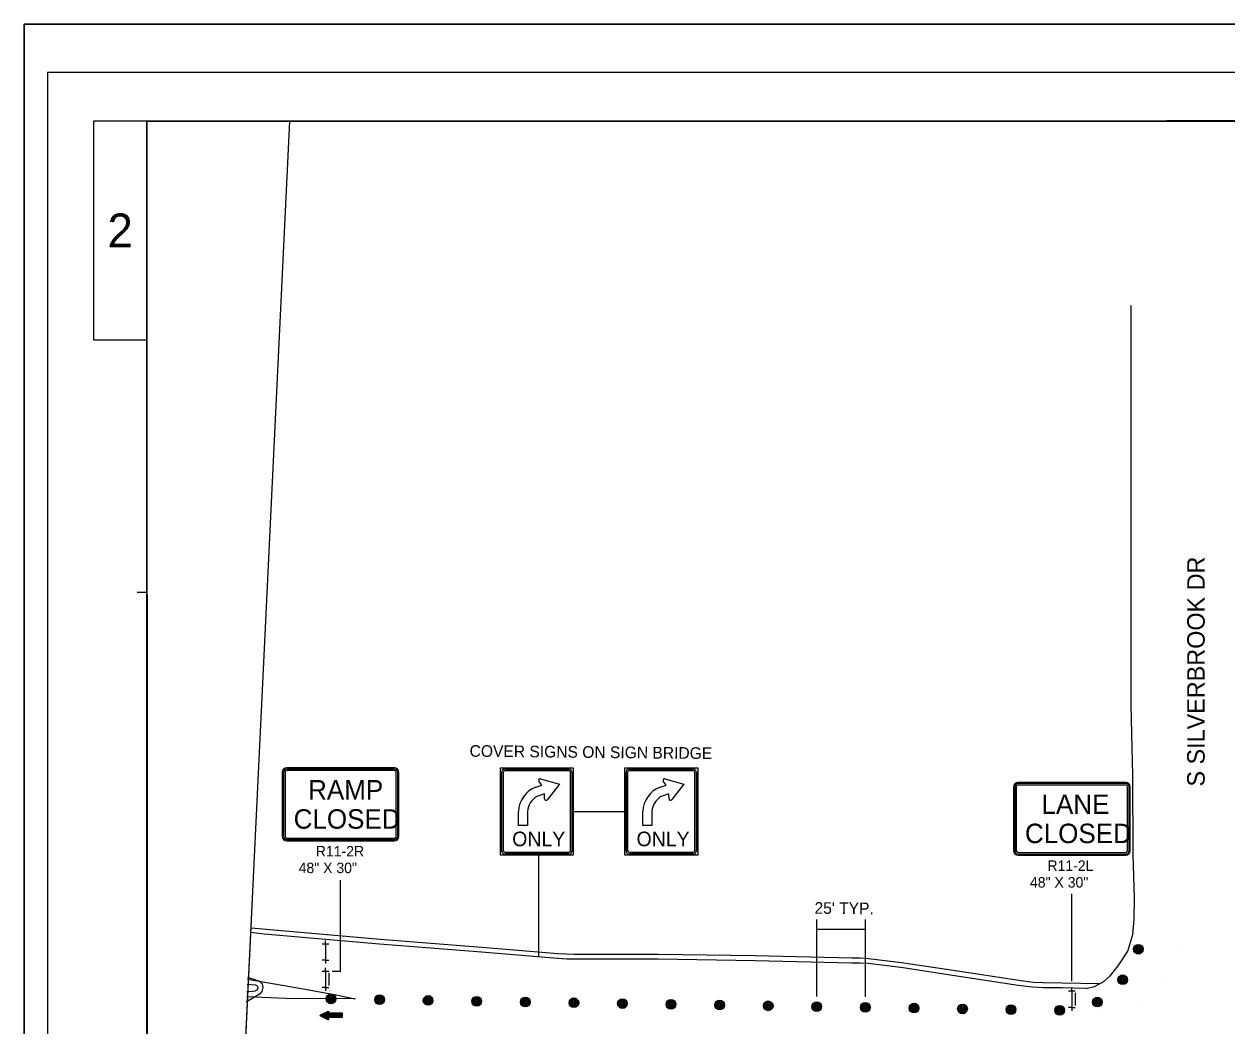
# Model space of a CAD drawing. Extents: x 360065 to 362124, y 174333 to 175433.
# Drawn here: x 360424 to 361043, y 174917 to 175433 of the extents above; entities that cross this region are included whole.
import ezdxf

# ---------------------------------------------------------------- set-up
doc = ezdxf.new("R2010")
doc.units = 0
for name, color, linetype in [('Default', 7, 'Continuous'), ('P_ALI_100_PIData', 7, 'Continuous'), ('P_ALI_100_Sta', 7, 'Continuous'), ('P_ALI_20', 7, 'Continuous'), ('P_ALI_200_Equation', 7, 'Continuous'), ('P_ALI_20_Equation', 7, 'Continuous'), ('P_ALI_20_Sta', 7, 'Continuous'), ('P_ALI_20_Tic', 7, 'Continuous'), ('P_ALI_500_PIData', 7, 'Continuous'), ('P_ALI_500_Sta', 7, 'Continuous'), ('P_ALI_50_Equation', 7, 'Continuous'), ('P_ALI_50_Tic', 7, 'Continuous'), ('P_TC_Drums_100_50', 7, 'Continuous')]:
    doc.layers.add(name, color=color, linetype=linetype)

msp = doc.modelspace()

# ---------------------------------------------------------------- linework, layer by layer
for p, q in [((360424.11, 175382.95), (360424.11, 175432.95)), ((360424.11, 175432.95), (360474.11, 175432.95)), ((360487.36, 175382.95), (362062.36, 175382.95)), ((360487.36, 174382.95), (360487.36, 175382.95)), ((360487.36, 175140.45), (360482.36, 175140.45))]:
    msp.add_line(p, q)
msp.add_lwpolyline([(360487.36, 175382.95), (360459.86, 175382.95), (360459.86, 175270.45), (360487.36, 175270.45)], close=True)
at = {"layer": 'Default'}
msp.add_lwpolyline([(362007.43, 175382.95), (362007.43, 174984.32), (362007.43, 174408.5), (360513.97, 174407.95), (360560.89, 175382.95)], close=True, dxfattribs=at)
msp.add_lwpolyline([(362007.43, 175382.95), (362007.43, 174984.32), (362007.43, 174408.5), (360513.97, 174407.95), (360560.89, 175382.95)], close=True, dxfattribs=at)
msp.add_lwpolyline([(362007.43, 175382.95), (362007.43, 174984.32), (362007.43, 174408.5), (360513.97, 174407.95), (360560.89, 175382.95)], close=True, dxfattribs=at)
at = {"layer": 'P_ALI_100_PIData'}
for p, q in [((360704.39, 175048.72), (360671.58, 175048.72)), ((360768.37, 175048.72), (360735.56, 175048.72)), ((360670.64, 175047.79), (360670.64, 175007.47)), ((360705.33, 175007.47), (360705.33, 175047.79)), ((360734.62, 175047.79), (360734.62, 175007.47)), ((360769.31, 175007.47), (360769.31, 175047.79)), ((360706.74, 175027.63), (360733.22, 175027.63)), ((360671.58, 175006.54), (360704.39, 175006.54)), ((360735.56, 175006.54), (360768.37, 175006.54)), ((360688.98, 174952.75), (360688.98, 175005.13)), ((360586.99, 174945.53), (360586.99, 174992.36)), ((360963.29, 174940.29), (360963.29, 174985.23)), ((360832, 174932.37), (360832, 174972.09)), ((360857, 174932.28), (360857, 174972.09)), ((360832, 174967.09), (360857, 174967.09)), ((360582.64, 174945.53), (360586.99, 174945.53))]:
    msp.add_line(p, q, dxfattribs=at)
for centre, start, end in [((360671.58, 175047.79), 90, 180), ((360704.39, 175047.79), 360, 90), ((360735.56, 175047.79), 90, 180), ((360768.37, 175047.79), 360, 90), ((360671.58, 175007.47), 180, 270), ((360704.39, 175007.47), 270, 0), ((360735.56, 175007.47), 180, 270), ((360768.37, 175007.47), 270, 0)]:
    msp.add_arc(centre, 0.938, start, end, dxfattribs=at)
at = {"layer": 'P_ALI_100_Sta'}
for p, q in [((360577.47, 174959.58), (360579.17, 174959.58)), ((360579.17, 174959.58), (360579.17, 174961.28)), ((360579.17, 174959.58), (360580.87, 174959.58)), ((360579.17, 174959.58), (360579.17, 174951.08)), ((361019.91, 174956.41), (361019.91, 174956.41)), ((360579.17, 174951.08), (360577.47, 174951.08)), ((360579.17, 174951.08), (360580.87, 174951.08)), ((360579.17, 174951.08), (360579.17, 174949.38)), ((360577.47, 174945.53), (360579.17, 174945.53)), ((360579.17, 174945.53), (360579.17, 174947.23)), ((360579.17, 174945.53), (360580.87, 174945.53)), ((360579.17, 174945.53), (360579.17, 174937.03)), ((360580.87, 174944.53), (360580.87, 174938.03)), ((361011.91, 174940.66), (361011.91, 174940.66)), ((360579.17, 174937.03), (360577.47, 174937.03)), ((360579.17, 174937.03), (360580.87, 174937.03)), ((360579.17, 174937.03), (360579.17, 174935.33)), ((360961.59, 174935.29), (360963.29, 174935.29)), ((360963.29, 174935.29), (360963.29, 174936.99)), ((360963.29, 174935.29), (360964.99, 174935.29)), ((360963.29, 174935.29), (360963.29, 174926.79)), ((360964.99, 174934.29), (360964.99, 174927.79)), ((360604.53, 174930.86), (360604.53, 174930.86)), ((360629.53, 174930.42), (360629.53, 174930.42)), ((360654.53, 174930.02), (360654.53, 174930.02)), ((360679.52, 174929.63), (360679.52, 174929.63)), ((360704.52, 174929.23), (360704.52, 174929.23)), ((360729.52, 174928.83), (360729.52, 174928.83)), ((360754.51, 174928.44), (360754.51, 174928.44)), ((360779.51, 174928.04), (360779.51, 174928.04)), ((360804.51, 174927.65), (360804.51, 174927.65)), ((360829.5, 174927.26), (360829.5, 174927.26)), ((360854.5, 174926.87), (360854.5, 174926.87)), ((360879.5, 174926.48), (360879.5, 174926.48)), ((360904.49, 174926.09), (360904.49, 174926.09)), ((360929.49, 174925.69), (360929.49, 174925.69)), ((360954.49, 174925.3), (360954.49, 174925.3)), ((360963.29, 174926.79), (360961.59, 174926.79)), ((360963.29, 174926.79), (360964.99, 174926.79)), ((360963.29, 174926.79), (360963.29, 174925.09)), ((360979.49, 174924.91), (360979.49, 174924.91)), ((360998.84, 174929.19), (360998.84, 174929.19))]:
    msp.add_line(p, q, dxfattribs=at)
for centre, radius in [((360997.42, 174956.76), 2.5), ((360997.42, 174956.76), 2), ((360997.42, 174956.76), 1.5), ((360997.42, 174956.76), 1), ((360997.42, 174956.76), 0.5), ((360997.42, 174956.76), 0.25), ((360989.42, 174941.02), 2.5), ((360989.42, 174941.02), 2), ((360989.42, 174941.02), 1.5), ((360989.42, 174941.02), 1), ((360989.42, 174941.02), 0.5), ((360989.42, 174941.02), 0.25), ((360582.04, 174931.21), 2.5), ((360582.04, 174931.21), 2), ((360582.04, 174931.21), 1.5), ((360582.04, 174931.21), 1), ((360582.04, 174931.21), 0.5), ((360582.04, 174931.21), 0.25), ((360607.03, 174930.78), 2.5), ((360607.03, 174930.78), 2), ((360607.03, 174930.78), 1.5), ((360607.03, 174930.78), 1), ((360607.03, 174930.78), 0.5), ((360607.03, 174930.78), 0.25), ((360632.03, 174930.38), 2.5), ((360632.03, 174930.38), 2), ((360632.03, 174930.38), 1.5), ((360632.03, 174930.38), 1), ((360657.03, 174929.98), 2.5), ((360657.03, 174929.98), 2), ((360657.03, 174929.98), 1.5), ((360657.03, 174929.98), 1), ((360682.02, 174929.58), 2.5), ((360682.02, 174929.58), 2), ((360682.02, 174929.58), 1.5), ((360707.02, 174929.18), 2.5), ((360707.02, 174929.18), 2), ((360732.02, 174928.79), 2.5), ((360976.35, 174929.54), 2.5), ((360976.35, 174929.54), 2), ((360976.35, 174929.54), 1.5), ((360632.03, 174930.38), 0.5), ((360632.03, 174930.38), 0.25), ((360657.03, 174929.98), 0.5), ((360657.03, 174929.98), 0.25), ((360682.02, 174929.58), 1), ((360682.02, 174929.58), 0.5), ((360682.02, 174929.58), 0.25), ((360707.02, 174929.18), 1.5), ((360707.02, 174929.18), 1), ((360707.02, 174929.18), 0.5), ((360707.02, 174929.18), 0.25), ((360732.02, 174928.79), 2), ((360732.02, 174928.79), 1.5), ((360732.02, 174928.79), 1), ((360732.02, 174928.79), 0.5), ((360732.02, 174928.79), 0.25), ((360757.01, 174928.4), 2.5), ((360757.01, 174928.4), 2), ((360757.01, 174928.4), 1.5), ((360757.01, 174928.4), 1), ((360757.01, 174928.4), 0.5), ((360757.01, 174928.4), 0.25), ((360782.01, 174928.01), 2.5), ((360782.01, 174928.01), 2), ((360782.01, 174928.01), 1.5), ((360782.01, 174928.01), 1), ((360782.01, 174928.01), 0.5), ((360782.01, 174928.01), 0.25), ((360807.01, 174927.61), 2.5), ((360807.01, 174927.61), 2), ((360807.01, 174927.61), 1.5), ((360807.01, 174927.61), 1), ((360807.01, 174927.61), 0.5), ((360807.01, 174927.61), 0.25), ((360832, 174927.22), 2.5), ((360832, 174927.22), 2), ((360832, 174927.22), 1.5), ((360832, 174927.22), 1), ((360832, 174927.22), 0.5), ((360832, 174927.22), 0.25), ((360857, 174926.83), 2.5), ((360857, 174926.83), 2), ((360857, 174926.83), 1.5), ((360857, 174926.83), 1), ((360857, 174926.83), 0.5), ((360857, 174926.83), 0.25), ((360882, 174926.44), 2.5), ((360882, 174926.44), 2), ((360882, 174926.44), 1.5), ((360882, 174926.44), 1), ((360882, 174926.44), 0.5), ((360882, 174926.44), 0.25), ((360906.99, 174926.05), 2.5), ((360906.99, 174926.05), 2), ((360906.99, 174926.05), 1.5), ((360906.99, 174926.05), 1), ((360906.99, 174926.05), 0.5), ((360906.99, 174926.05), 0.25), ((360931.99, 174925.65), 2.5), ((360931.99, 174925.65), 2), ((360931.99, 174925.65), 1.5), ((360931.99, 174925.65), 1), ((360931.99, 174925.65), 0.5), ((360931.99, 174925.65), 0.25), ((360956.99, 174925.26), 2.5), ((360956.99, 174925.26), 2), ((360956.99, 174925.26), 1.5), ((360956.99, 174925.26), 1), ((360956.99, 174925.26), 0.5), ((360956.99, 174925.26), 0.25), ((360976.35, 174929.54), 1), ((360976.35, 174929.54), 0.5), ((360976.35, 174929.54), 0.25)]:
    msp.add_circle(centre, radius, dxfattribs=at)
at = {"layer": 'P_ALI_20'}
for points in [[(360424.11, 174332.95), (362124.11, 174332.95), (362124.11, 175432.95), (360424.11, 175432.95)], [(360436.11, 174357.95), (362091.11, 174357.95), (362091.11, 175407.95), (360436.11, 175407.95)]]:
    msp.add_lwpolyline(points, close=True, dxfattribs=at)
at = {"layer": 'P_ALI_200_Equation'}
msp.add_lwpolyline([(360424.11, 175432.95), (362124.11, 175432.95), (362124.11, 174332.95), (360424.11, 174332.95), (360424.11, 175432.95)], dxfattribs=at)
at = {"layer": 'P_ALI_20_Equation'}
msp.add_line((360993.75, 175082.17), (360993.75, 175288.17), dxfattribs=at)
for points in [[(360970.58, 174936.56), (360970.58, 174936.56), (360970.58, 174936.56), (360970.58, 174936.56), (360970.58, 174936.56), (360974.85, 174937.53), (360979.64, 174940.2), (360983.1, 174943.25), (360987.12, 174948.28), (360992.14, 174955.78), (360994.64, 174964.37), (360995.33, 174972.21), (360995.44, 174983.02), (360994.88, 175005.27), (360994.61, 175046.09), (360993.75, 175082.17)], [(360970.58, 174936.56), (360970.58, 174936.56), (360958.29, 174936.82), (360948.46, 174936.95), (360943.08, 174937.2), (360935.6, 174938.11), (360901.84, 174943.28), (360876.44, 174947.15), (360868.17, 174948.17), (360858.37, 174949.37), (360854.23, 174949.58), (360850.06, 174949.59), (360800.28, 174950.8), (360750.37, 174951.56), (360706.92, 174951.58), (360703.36, 174951.63), (360698.54, 174951.96), (360659.5, 174955.21), (360607.07, 174959.3), (360547.62, 174964.46), (360540.79, 174965.31)], [(360977.33, 174938.91), (360958.33, 174939.32), (360948.54, 174939.44), (360943.29, 174939.69), (360935.94, 174940.59), (360902.22, 174945.76), (360876.78, 174949.63), (360868.48, 174950.65), (360858.59, 174951.86), (360854.3, 174952.08), (360850.1, 174952.09), (360800.32, 174953.3), (360750.39, 174954.06), (360706.94, 174954.08), (360703.46, 174954.13), (360698.73, 174954.45), (360659.71, 174957.7), (360607.27, 174961.79), (360540.9, 174967.55)], [(360539.08, 174942.35), (360545.27, 174940.34), (360546.55, 174938.92), (360546.96, 174936.98), (360546.52, 174935.08), (360545.21, 174933.63), (360538.46, 174929.54)], [(360539.03, 174941.35), (360565.88, 174936.74), (360583.83, 174933.52), (360594.49, 174931.26), (360558.8, 174931.46), (360538.59, 174932.2)], [(360538.9, 174938.81), (360543.16, 174938.4), (360543.86, 174938.17), (360544.24, 174937.75), (360544.4, 174937.01), (360544.23, 174936.28), (360543.6, 174935.58), (360542.92, 174935.17), (360541.9, 174935), (360538.71, 174934.83)]]:
    msp.add_lwpolyline(points, dxfattribs=at)
at = {"layer": 'P_ALI_20_Sta'}
msp.add_lwpolyline([(360424.11, 175432.95), (362124.11, 175432.95), (362124.11, 174332.95), (360424.11, 174332.95)], close=True, dxfattribs=at)
at = {"layer": 'P_ALI_20_Tic'}
msp.add_line((360531.68, 174775.82), (360541.63, 174982.64), dxfattribs=at)
at = {"layer": 'P_ALI_500_PIData'}
for p, q in [((360576.29, 174922.72), (360580.69, 174924.93)), ((360580.69, 174924.93), (360580.69, 174920.43)), ((360576.29, 174922.72), (360580.69, 174920.43)), ((360587.81, 174922.91), (360576.67, 174922.91)), ((360587.81, 174922.46), (360576.79, 174922.46)), ((360587.81, 174923.36), (360577.56, 174923.36)), ((360587.81, 174922.01), (360577.66, 174922.01)), ((360580.66, 174923.81), (360578.46, 174923.81)), ((360580.66, 174921.56), (360578.52, 174921.56)), ((360580.66, 174924.26), (360579.35, 174924.26)), ((360580.66, 174921.11), (360579.39, 174921.11)), ((360580.66, 174924.71), (360580.24, 174924.71)), ((360580.66, 174920.66), (360580.25, 174920.66)), ((360587.81, 174923.81), (360580.69, 174923.81)), ((360587.81, 174921.56), (360580.69, 174921.56)), ((360587.81, 174923.81), (360587.81, 174921.56)), ((360587.81, 174922.68), (360587.81, 174922.68))]:
    msp.add_line(p, q, dxfattribs=at)
at = {"layer": 'P_ALI_500_Sta'}
for p, q in [((360614.66, 175050.07), (360559.33, 175050.07)), ((360614.66, 175049.45), (360559.33, 175049.45)), ((360614.66, 175048.67), (360559.33, 175048.67)), ((360556.98, 175047.73), (360556.98, 175014.91)), ((360557.61, 175047.73), (360557.61, 175014.91)), ((360558.39, 175047.71), (360558.39, 175014.91)), ((360615.6, 175014.91), (360615.6, 175047.73)), ((360616.38, 175014.91), (360616.38, 175047.73)), ((360617, 175014.91), (360617, 175047.73)), ((360990.95, 175042.64), (360935.62, 175042.64)), ((360933.28, 175040.3), (360933.28, 175007.48)), ((360933.9, 175040.3), (360933.9, 175007.48)), ((360934.68, 175040.28), (360934.68, 175007.48)), ((360990.95, 175042.02), (360935.62, 175042.02)), ((360990.95, 175041.24), (360935.62, 175041.24)), ((360991.89, 175007.48), (360991.89, 175040.3)), ((360992.67, 175007.48), (360992.67, 175040.3)), ((360993.3, 175007.48), (360993.3, 175040.3)), ((360559.33, 175013.97), (360614.66, 175013.97)), ((360559.33, 175013.19), (360614.66, 175013.19)), ((360559.33, 175012.56), (360614.66, 175012.56)), ((360935.62, 175006.54), (360990.95, 175006.54)), ((360935.62, 175005.76), (360990.95, 175005.76)), ((360935.62, 175005.13), (360990.95, 175005.13))]:
    msp.add_line(p, q, dxfattribs=at)
for centre, radius, start, end in [((360559.33, 175047.73), 2.34, 90, 180), ((360559.33, 175047.73), 1.72, 90, 180), ((360559.33, 175047.73), 0.938, 90, 181.0779), ((360614.66, 175047.73), 2.34, 0, 90), ((360614.66, 175047.73), 1.72, 0, 90), ((360614.66, 175047.73), 0.938, 0, 90), ((360935.62, 175040.3), 2.34, 90, 180), ((360990.95, 175040.3), 2.34, 0, 90), ((360935.62, 175040.3), 1.72, 90, 180), ((360935.62, 175040.3), 0.938, 90, 181.0779), ((360990.95, 175040.3), 1.72, 0, 90), ((360990.95, 175040.3), 0.938, 0, 90), ((360559.33, 175014.91), 2.34, 180, 270), ((360559.33, 175014.91), 1.72, 180, 270), ((360559.33, 175014.91), 0.938, 180, 270), ((360614.66, 175014.91), 0.938, 270, 360), ((360614.66, 175014.91), 1.72, 270, 360), ((360614.66, 175014.91), 2.34, 270, 360), ((360935.62, 175007.48), 2.34, 180, 270), ((360935.62, 175007.48), 1.72, 180, 270), ((360935.62, 175007.48), 0.938, 180, 270), ((360990.95, 175007.48), 0.938, 270, 360), ((360990.95, 175007.48), 1.72, 270, 360), ((360990.95, 175007.48), 2.34, 270, 360)]:
    msp.add_arc(centre, radius, start, end, dxfattribs=at)
at = {"layer": 'P_ALI_50_Tic'}
msp.add_lwpolyline([(362062.02, 175383.5), (360487.36, 175382.95), (360487.7, 174407.95)], dxfattribs=at)
at = {"layer": 'P_TC_Drums_100_50'}
for p, q in [((360669.24, 175005.13), (360669.24, 175050.13)), ((360669.24, 175050.13), (360706.74, 175050.13)), ((360671.58, 175049.51), (360704.39, 175049.51)), ((360671.58, 175048.72), (360704.39, 175048.72)), ((360706.74, 175050.13), (360706.74, 175005.13)), ((360733.22, 175005.13), (360733.22, 175050.13)), ((360733.22, 175050.13), (360770.72, 175050.13)), ((360735.56, 175049.51), (360768.37, 175049.51)), ((360735.56, 175048.72), (360768.37, 175048.72)), ((360770.72, 175050.13), (360770.72, 175005.13)), ((360669.86, 175007.47), (360669.86, 175047.79)), ((360670.64, 175007.47), (360670.64, 175047.79)), ((360690.46, 175041.21), (360689.04, 175043.31)), ((360689.9, 175044.5), (360699.55, 175041.69)), ((360705.33, 175047.79), (360705.33, 175007.47)), ((360706.11, 175047.79), (360706.11, 175007.47)), ((360733.84, 175007.47), (360733.84, 175047.79)), ((360734.62, 175007.47), (360734.62, 175047.79)), ((360754.44, 175041.21), (360753.02, 175043.31)), ((360753.88, 175044.5), (360763.53, 175041.69)), ((360769.31, 175047.79), (360769.31, 175007.47)), ((360770.09, 175047.79), (360770.09, 175007.47)), ((360687.48, 175040.24), (360690.46, 175041.21)), ((360691.9, 175036.75), (360687.93, 175035.29)), ((360691.99, 175034.21), (360691.9, 175036.75)), ((360699.55, 175041.69), (360693.39, 175033.76)), ((360751.46, 175040.24), (360754.44, 175041.21)), ((360755.88, 175036.75), (360751.92, 175035.29)), ((360755.97, 175034.21), (360755.88, 175036.75)), ((360763.53, 175041.69), (360757.37, 175033.76)), ((360678.46, 175020.44), (360678.47, 175027.63)), ((360683.16, 175027.63), (360683.14, 175020.44)), ((360742.44, 175020.44), (360742.45, 175027.63)), ((360747.14, 175027.63), (360747.12, 175020.44)), ((360683.14, 175020.44), (360678.46, 175020.44)), ((360747.12, 175020.44), (360742.44, 175020.44)), ((360704.39, 175006.54), (360671.58, 175006.54)), ((360704.39, 175005.76), (360671.58, 175005.76)), ((360768.37, 175006.54), (360735.56, 175006.54)), ((360768.37, 175005.76), (360735.56, 175005.76)), ((360706.74, 175005.13), (360669.24, 175005.13)), ((360770.72, 175005.13), (360733.22, 175005.13))]:
    msp.add_line(p, q, dxfattribs=at)
for centre, radius, start, end in [((360671.58, 175047.79), 1.72, 90, 180), ((360671.58, 175047.79), 0.938, 90, 180), ((360704.39, 175047.79), 1.72, 0, 90), ((360704.39, 175047.79), 0.938, 0, 90), ((360735.56, 175047.79), 1.72, 90, 180), ((360735.56, 175047.79), 0.938, 90, 180), ((360768.37, 175047.79), 1.72, 0, 90), ((360768.37, 175047.79), 0.938, 0, 90), ((360689.68, 175043.75), 0.781, 73.78835, 214.03143), ((360753.66, 175043.75), 0.781, 73.78835, 214.03143), ((360692.67, 175027.01), 14.22, 111.42573, 177.48069), ((360756.66, 175027.01), 14.22, 111.42573, 177.48069), ((360692.67, 175027.01), 9.53, 119.45918, 176.2402), ((360692.77, 175034.24), 0.781, 181.95236, 322.16006), ((360756.66, 175027.01), 9.53, 119.45918, 176.2402), ((360756.75, 175034.24), 0.781, 181.95236, 322.16006), ((360671.58, 175007.47), 1.72, 180, 270), ((360671.58, 175007.47), 0.938, 180, 270), ((360704.39, 175007.47), 1.72, 270, 0), ((360704.39, 175007.47), 0.938, 270, 0), ((360735.56, 175007.47), 1.72, 180, 270), ((360735.56, 175007.47), 0.938, 180, 270), ((360768.37, 175007.47), 1.72, 270, 0), ((360768.37, 175007.47), 0.938, 270, 0)]:
    msp.add_arc(centre, radius, start, end, dxfattribs=at)

# ---------------------------------------------------------------- texts
msp.add_text('2', height=17.5, rotation=360).set_placement((360467.07, 175317.95))
at = {"layer": 'P_ALI_500_Sta'}
for s, height, p in [('RAMP', 10, (360570.28, 175033.82)), ('LANE', 10, (360947.64, 175026.39)), ('CLOSED', 10, (360562.84, 175018.81)), ('CLOSED', 10, (360939.13, 175011.38)), ('R11-2R', 5.4, (360574.22, 175004.5)), ('48" X 30"', 5.4, (360565.4, 174995.92)), ('R11-2L', 5.4, (360950.67, 174997.06)), ('48" X 30"', 5.4, (360941.7, 174988.49))]:
    msp.add_text(s, height=height, dxfattribs=at).set_placement(p)
at = {"layer": 'P_ALI_50_Equation'}
for s, height, rotation, p in [('S SILVERBROOK DR', 9, 90, (361031.6, 175040.48)), ('COVER SIGNS ON SIGN BRIDGE', 6, 359.43821, (360653.35, 175055.85)), ("25' TYP.", 6, 359.43821, (360830.81, 174975.02))]:
    msp.add_text(s, height=height, rotation=rotation, dxfattribs=at).set_placement(p)
at = {"layer": 'P_TC_Drums_100_50'}
for p in [(360675.28, 175009.78), (360739.26, 175009.78)]:
    msp.add_text('ONLY', height=7.5, dxfattribs=at).set_placement(p)

doc.saveas('drawing.dxf')
